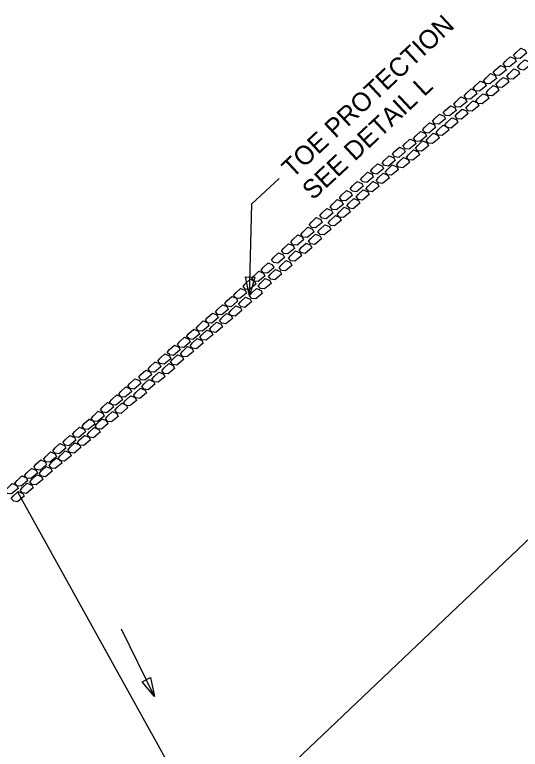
# Model space of a CAD drawing. Extents: x 2384780 to 2405432, y 547869 to 573706.
# Drawn here: x 2398296.7 to 2398431.5, y 559969.6 to 560165.6 of the extents above; entities that cross this region are included whole.
import ezdxf

# ---------------------------------------------------------------- set-up
doc = ezdxf.new("R2010")
doc.units = 0
for name, color, linetype in [('Old_Level_1', 7, 'Continuous'), ('Old_Level_19', 7, 'Continuous'), ('Old_Level_20', 7, 'Continuous'), ('Old_Level_5', 7, 'Continuous')]:
    doc.layers.add(name, color=color, linetype=linetype)

msp = doc.modelspace()

# ---------------------------------------------------------------- linework, layer by layer
at = {"layer": 'Old_Level_1'}
msp.add_line((2398405.81, 559842.88), (2398297.53, 560038.23), dxfattribs=at)
at = {"layer": 'Old_Level_19'}
msp.add_line((2398244.74, 559846.05), (2398525.67, 560113.13), dxfattribs=at)
at = {"layer": 'Old_Level_20'}
for points in [[(2398429.74, 560154.75), (2398430.34, 560155.49), (2398431.61, 560156.68), (2398432.83, 560156.16), (2398433.18, 560155.39), (2398431.43, 560153.93), (2398430.38, 560154.07), (2398429.74, 560154.75)], [(2398426.93, 560152.52), (2398427.53, 560153.26), (2398428.8, 560154.44), (2398430.02, 560153.93), (2398430.37, 560153.16), (2398428.62, 560151.7), (2398427.57, 560151.83), (2398426.93, 560152.52)], [(2398430.79, 560151.68), (2398431.39, 560152.41), (2398432.66, 560153.6), (2398433.88, 560153.08), (2398434.23, 560152.31), (2398432.47, 560150.85), (2398431.43, 560150.99), (2398430.79, 560151.68)], [(2398424.31, 560150.21), (2398424.91, 560150.94), (2398426.19, 560152.13), (2398427.41, 560151.61), (2398427.75, 560150.84), (2398426, 560149.38), (2398424.96, 560149.52), (2398424.31, 560150.21)], [(2398427.9, 560149.25), (2398428.5, 560149.99), (2398429.77, 560151.17), (2398430.99, 560150.66), (2398431.34, 560149.89), (2398429.59, 560148.43), (2398428.54, 560148.56), (2398427.9, 560149.25)], [(2398421.69, 560147.98), (2398422.29, 560148.72), (2398423.56, 560149.91), (2398424.78, 560149.39), (2398425.13, 560148.62), (2398423.37, 560147.16), (2398422.33, 560147.3), (2398421.69, 560147.98)], [(2398418.95, 560146.03), (2398419.55, 560146.77), (2398420.83, 560147.95), (2398422.05, 560147.44), (2398422.39, 560146.67), (2398420.64, 560145.21), (2398419.59, 560145.34), (2398418.95, 560146.03)], [(2398425, 560147.01), (2398425.6, 560147.75), (2398426.87, 560148.93), (2398428.09, 560148.42), (2398428.44, 560147.65), (2398426.68, 560146.19), (2398425.64, 560146.32), (2398425, 560147.01)], [(2398416.51, 560143.91), (2398417.11, 560144.65), (2398418.38, 560145.84), (2398419.6, 560145.32), (2398419.95, 560144.55), (2398418.19, 560143.09), (2398417.15, 560143.23), (2398416.51, 560143.91)], [(2398422.38, 560144.79), (2398422.98, 560145.52), (2398424.25, 560146.71), (2398425.47, 560146.19), (2398425.82, 560145.42), (2398424.06, 560143.96), (2398423.02, 560144.1), (2398422.38, 560144.79)], [(2398413.78, 560141.78), (2398414.38, 560142.51), (2398415.66, 560143.7), (2398416.88, 560143.18), (2398417.22, 560142.41), (2398415.47, 560140.95), (2398414.42, 560141.09), (2398413.78, 560141.78)], [(2398419.65, 560142.65), (2398420.25, 560143.39), (2398421.52, 560144.57), (2398422.74, 560144.06), (2398423.09, 560143.29), (2398421.34, 560141.83), (2398420.29, 560141.96), (2398419.65, 560142.65)], [(2398410.98, 560139.45), (2398411.58, 560140.19), (2398412.85, 560141.37), (2398414.07, 560140.86), (2398414.42, 560140.09), (2398412.66, 560138.63), (2398411.62, 560138.76), (2398410.98, 560139.45)], [(2398417.01, 560140.71), (2398417.61, 560141.44), (2398418.88, 560142.63), (2398420.1, 560142.11), (2398420.45, 560141.34), (2398418.69, 560139.88), (2398417.65, 560140.02), (2398417.01, 560140.71)], [(2398414.1, 560138.56), (2398414.7, 560139.29), (2398415.97, 560140.48), (2398417.19, 560139.96), (2398417.54, 560139.19), (2398415.79, 560137.73), (2398414.74, 560137.87), (2398414.1, 560138.56)], [(2398408.08, 560137.21), (2398408.68, 560137.94), (2398409.95, 560139.13), (2398411.17, 560138.61), (2398411.52, 560137.85), (2398409.76, 560136.39), (2398408.72, 560136.52), (2398408.08, 560137.21)], [(2398411.39, 560136.24), (2398411.99, 560136.97), (2398413.26, 560138.16), (2398414.48, 560137.64), (2398414.83, 560136.87), (2398413.07, 560135.41), (2398412.03, 560135.55), (2398411.39, 560136.24)], [(2398405.46, 560134.89), (2398406.06, 560135.63), (2398407.33, 560136.82), (2398408.55, 560136.3), (2398408.9, 560135.53), (2398407.14, 560134.07), (2398406.1, 560134.21), (2398405.46, 560134.89)], [(2398409.03, 560134.22), (2398409.63, 560134.95), (2398410.9, 560136.14), (2398412.12, 560135.62), (2398412.47, 560134.85), (2398410.71, 560133.39), (2398409.67, 560133.53), (2398409.03, 560134.22)], [(2398403.03, 560132.59), (2398403.63, 560133.33), (2398404.9, 560134.52), (2398406.12, 560134), (2398406.47, 560133.23), (2398404.71, 560131.77), (2398403.67, 560131.9), (2398403.03, 560132.59)], [(2398406.4, 560132.09), (2398407, 560132.82), (2398408.27, 560134.01), (2398409.49, 560133.49), (2398409.84, 560132.72), (2398408.08, 560131.26), (2398407.04, 560131.4), (2398406.4, 560132.09)], [(2398400.21, 560130.54), (2398400.8, 560131.28), (2398402.08, 560132.46), (2398403.3, 560131.95), (2398403.65, 560131.18), (2398401.89, 560129.72), (2398400.85, 560129.85), (2398400.21, 560130.54)], [(2398403.58, 560130.04), (2398404.18, 560130.77), (2398405.45, 560131.96), (2398406.67, 560131.44), (2398407.02, 560130.67), (2398405.26, 560129.21), (2398404.22, 560129.35), (2398403.58, 560130.04)], [(2398397.39, 560128.4), (2398397.99, 560129.13), (2398399.26, 560130.32), (2398400.48, 560129.8), (2398400.83, 560129.04), (2398399.07, 560127.58), (2398398.03, 560127.71), (2398397.39, 560128.4)], [(2398401.15, 560127.64), (2398401.75, 560128.38), (2398403.02, 560129.57), (2398404.24, 560129.05), (2398404.59, 560128.28), (2398402.83, 560126.82), (2398401.79, 560126.95), (2398401.15, 560127.64)], [(2398394.68, 560126.08), (2398395.28, 560126.81), (2398396.55, 560128), (2398397.77, 560127.48), (2398398.12, 560126.71), (2398396.36, 560125.25), (2398395.32, 560125.39), (2398394.68, 560126.08)], [(2398391.59, 560123.92), (2398392.19, 560124.65), (2398393.46, 560125.84), (2398394.68, 560125.32), (2398395.03, 560124.55), (2398393.27, 560123.09), (2398392.23, 560123.23), (2398391.59, 560123.92)], [(2398398.51, 560125.6), (2398399.11, 560126.34), (2398400.38, 560127.53), (2398401.6, 560127.01), (2398401.95, 560126.24), (2398400.2, 560124.78), (2398399.15, 560124.92), (2398398.51, 560125.6)], [(2398395.5, 560123.63), (2398396.1, 560124.37), (2398397.37, 560125.56), (2398398.59, 560125.04), (2398398.94, 560124.27), (2398397.18, 560122.81), (2398396.14, 560122.95), (2398395.5, 560123.63)], [(2398388.87, 560121.69), (2398389.47, 560122.42), (2398390.74, 560123.61), (2398391.96, 560123.09), (2398392.31, 560122.32), (2398390.55, 560120.86), (2398389.51, 560121), (2398388.87, 560121.69)], [(2398393.06, 560121.42), (2398393.66, 560122.16), (2398394.93, 560123.35), (2398396.15, 560122.83), (2398396.5, 560122.06), (2398394.74, 560120.6), (2398393.7, 560120.74), (2398393.06, 560121.42)], [(2398386.13, 560119.22), (2398386.73, 560119.96), (2398388, 560121.14), (2398389.22, 560120.63), (2398389.57, 560119.86), (2398387.81, 560118.4), (2398386.77, 560118.53), (2398386.13, 560119.22)], [(2398390.34, 560119.19), (2398390.94, 560119.93), (2398392.21, 560121.12), (2398393.43, 560120.6), (2398393.78, 560119.83), (2398392.03, 560118.37), (2398390.98, 560118.51), (2398390.34, 560119.19)], [(2398383.25, 560116.78), (2398383.85, 560117.51), (2398385.13, 560118.7), (2398386.35, 560118.18), (2398386.69, 560117.42), (2398384.94, 560115.96), (2398383.89, 560116.09), (2398383.25, 560116.78)], [(2398387.72, 560117), (2398388.32, 560117.74), (2398389.59, 560118.92), (2398390.81, 560118.41), (2398391.16, 560117.64), (2398389.4, 560116.18), (2398388.36, 560116.31), (2398387.72, 560117)], [(2398380.82, 560114.37), (2398381.42, 560115.1), (2398382.69, 560116.29), (2398383.91, 560115.77), (2398384.26, 560115), (2398382.51, 560113.54), (2398381.46, 560113.68), (2398380.82, 560114.37)], [(2398385.28, 560114.68), (2398385.88, 560115.42), (2398387.15, 560116.6), (2398388.37, 560116.09), (2398388.72, 560115.32), (2398386.97, 560113.86), (2398385.92, 560113.99), (2398385.28, 560114.68)], [(2398378.03, 560112.02), (2398378.63, 560112.76), (2398379.9, 560113.94), (2398381.12, 560113.43), (2398381.47, 560112.66), (2398379.71, 560111.2), (2398378.67, 560111.33), (2398378.03, 560112.02)], [(2398382.67, 560112.34), (2398383.27, 560113.08), (2398384.54, 560114.27), (2398385.76, 560113.75), (2398386.11, 560112.98), (2398384.35, 560111.52), (2398383.31, 560111.66), (2398382.67, 560112.34)], [(2398380.31, 560110.12), (2398380.91, 560110.85), (2398382.18, 560112.04), (2398383.4, 560111.52), (2398383.75, 560110.76), (2398382, 560109.3), (2398380.95, 560109.43), (2398380.31, 560110.12)], [(2398375.24, 560109.58), (2398375.84, 560110.32), (2398377.11, 560111.51), (2398378.33, 560110.99), (2398378.68, 560110.22), (2398376.92, 560108.76), (2398375.88, 560108.9), (2398375.24, 560109.58)], [(2398373, 560107.01), (2398373.6, 560107.74), (2398374.87, 560108.93), (2398376.09, 560108.41), (2398376.44, 560107.64), (2398374.68, 560106.18), (2398373.64, 560106.32), (2398373, 560107.01)], [(2398377.52, 560107.68), (2398378.12, 560108.42), (2398379.4, 560109.6), (2398380.62, 560109.09), (2398380.96, 560108.32), (2398379.21, 560106.86), (2398378.17, 560106.99), (2398377.52, 560107.68)], [(2398370.28, 560104.93), (2398370.88, 560105.67), (2398372.15, 560106.86), (2398373.37, 560106.34), (2398373.72, 560105.57), (2398371.96, 560104.11), (2398370.92, 560104.25), (2398370.28, 560104.93)], [(2398375.01, 560105.18), (2398375.61, 560105.91), (2398376.88, 560107.1), (2398378.1, 560106.58), (2398378.45, 560105.81), (2398376.69, 560104.35), (2398375.65, 560104.49), (2398375.01, 560105.18)], [(2398367.84, 560102.61), (2398368.44, 560103.35), (2398369.71, 560104.53), (2398370.93, 560104.02), (2398371.28, 560103.25), (2398369.52, 560101.79), (2398368.48, 560101.92), (2398367.84, 560102.61)], [(2398372.49, 560102.76), (2398373.09, 560103.49), (2398374.36, 560104.68), (2398375.58, 560104.16), (2398375.93, 560103.39), (2398374.17, 560101.94), (2398373.13, 560102.07), (2398372.49, 560102.76)], [(2398365.14, 560100.18), (2398365.74, 560100.92), (2398367.01, 560102.1), (2398368.23, 560101.59), (2398368.58, 560100.82), (2398366.82, 560099.36), (2398365.78, 560099.49), (2398365.14, 560100.18)], [(2398369.68, 560100.68), (2398370.28, 560101.41), (2398371.55, 560102.6), (2398372.77, 560102.08), (2398373.12, 560101.32), (2398371.36, 560099.86), (2398370.32, 560099.99), (2398369.68, 560100.68)], [(2398362.37, 560097.48), (2398362.97, 560098.21), (2398364.24, 560099.4), (2398365.46, 560098.88), (2398365.81, 560098.12), (2398364.05, 560096.66), (2398363.01, 560096.79), (2398362.37, 560097.48)], [(2398367.17, 560098.08), (2398367.77, 560098.82), (2398369.04, 560100.01), (2398370.26, 560099.49), (2398370.61, 560098.72), (2398368.85, 560097.26), (2398367.81, 560097.4), (2398367.17, 560098.08)], [(2398359.93, 560095.25), (2398360.53, 560095.98), (2398361.8, 560097.17), (2398363.02, 560096.65), (2398363.37, 560095.88), (2398361.61, 560094.42), (2398360.57, 560094.56), (2398359.93, 560095.25)], [(2398364.37, 560095.74), (2398364.97, 560096.47), (2398366.25, 560097.66), (2398367.47, 560097.14), (2398367.81, 560096.37), (2398366.06, 560094.91), (2398365.02, 560095.05), (2398364.37, 560095.74)], [(2398357.57, 560093.11), (2398358.17, 560093.84), (2398359.44, 560095.03), (2398360.66, 560094.51), (2398361.01, 560093.75), (2398359.25, 560092.29), (2398358.21, 560092.42), (2398357.57, 560093.11)], [(2398361.59, 560093.3), (2398362.19, 560094.04), (2398363.46, 560095.22), (2398364.68, 560094.71), (2398365.03, 560093.94), (2398363.27, 560092.48), (2398362.23, 560092.61), (2398361.59, 560093.3)], [(2398355.05, 560090.69), (2398355.64, 560091.43), (2398356.92, 560092.61), (2398358.14, 560092.1), (2398358.49, 560091.33), (2398356.73, 560089.87), (2398355.69, 560090), (2398355.05, 560090.69)], [(2398359.26, 560090.63), (2398359.86, 560091.36), (2398361.14, 560092.55), (2398362.36, 560092.03), (2398362.7, 560091.26), (2398360.95, 560089.8), (2398359.9, 560089.94), (2398359.26, 560090.63)], [(2398352.69, 560088.55), (2398353.28, 560089.29), (2398354.56, 560090.48), (2398355.78, 560089.96), (2398356.12, 560089.19), (2398354.37, 560087.73), (2398353.33, 560087.87), (2398352.69, 560088.55)], [(2398356.37, 560088.36), (2398356.97, 560089.1), (2398358.25, 560090.29), (2398359.47, 560089.77), (2398359.81, 560089), (2398358.06, 560087.54), (2398357.02, 560087.68), (2398356.37, 560088.36)], [(2398350.2, 560086.34), (2398350.8, 560087.07), (2398352.08, 560088.26), (2398353.3, 560087.74), (2398353.64, 560086.97), (2398351.89, 560085.51), (2398350.85, 560085.65), (2398350.2, 560086.34)], [(2398353.76, 560086.03), (2398354.36, 560086.76), (2398355.63, 560087.95), (2398356.85, 560087.43), (2398357.2, 560086.67), (2398355.44, 560085.21), (2398354.4, 560085.34), (2398353.76, 560086.03)], [(2398347.52, 560084.12), (2398348.12, 560084.85), (2398349.39, 560086.04), (2398350.61, 560085.52), (2398350.96, 560084.75), (2398349.21, 560083.29), (2398348.16, 560083.43), (2398347.52, 560084.12)], [(2398351.3, 560083.97), (2398351.9, 560084.71), (2398353.17, 560085.9), (2398354.39, 560085.38), (2398354.74, 560084.61), (2398352.99, 560083.15), (2398351.94, 560083.29), (2398351.3, 560083.97)], [(2398345.04, 560082), (2398345.64, 560082.74), (2398346.91, 560083.92), (2398348.13, 560083.41), (2398348.48, 560082.64), (2398346.73, 560081.18), (2398345.68, 560081.31), (2398345.04, 560082)], [(2398348.63, 560081.7), (2398349.23, 560082.43), (2398350.5, 560083.62), (2398351.72, 560083.1), (2398352.07, 560082.34), (2398350.32, 560080.88), (2398349.27, 560081.01), (2398348.63, 560081.7)], [(2398342.52, 560079.79), (2398343.12, 560080.53), (2398344.4, 560081.72), (2398345.62, 560081.2), (2398345.96, 560080.43), (2398344.21, 560078.97), (2398343.17, 560079.11), (2398342.52, 560079.79)], [(2398346.04, 560079.57), (2398346.64, 560080.31), (2398347.91, 560081.5), (2398349.13, 560080.98), (2398349.48, 560080.21), (2398347.73, 560078.75), (2398346.68, 560078.89), (2398346.04, 560079.57)], [(2398340.06, 560077.64), (2398340.66, 560078.38), (2398341.93, 560079.57), (2398343.15, 560079.05), (2398343.5, 560078.28), (2398341.74, 560076.82), (2398340.7, 560076.96), (2398340.06, 560077.64)], [(2398343.47, 560077.31), (2398344.07, 560078.05), (2398345.35, 560079.23), (2398346.57, 560078.72), (2398346.91, 560077.95), (2398345.16, 560076.49), (2398344.12, 560076.62), (2398343.47, 560077.31)], [(2398337.37, 560075.53), (2398337.97, 560076.27), (2398339.24, 560077.46), (2398340.46, 560076.94), (2398340.81, 560076.17), (2398339.05, 560074.71), (2398338.01, 560074.85), (2398337.37, 560075.53)], [(2398340.9, 560075.15), (2398341.5, 560075.89), (2398342.77, 560077.07), (2398343.99, 560076.56), (2398344.34, 560075.79), (2398342.58, 560074.33), (2398341.54, 560074.46), (2398340.9, 560075.15)], [(2398334.86, 560073.22), (2398335.46, 560073.95), (2398336.73, 560075.14), (2398337.95, 560074.62), (2398338.3, 560073.85), (2398336.54, 560072.39), (2398335.5, 560072.53), (2398334.86, 560073.22)], [(2398338.21, 560072.99), (2398338.81, 560073.72), (2398340.08, 560074.91), (2398341.3, 560074.39), (2398341.65, 560073.62), (2398339.9, 560072.16), (2398338.85, 560072.3), (2398338.21, 560072.99)], [(2398332.23, 560071.06), (2398332.83, 560071.79), (2398334.1, 560072.98), (2398335.32, 560072.46), (2398335.67, 560071.69), (2398333.91, 560070.23), (2398332.87, 560070.37), (2398332.23, 560071.06)], [(2398329.73, 560068.91), (2398330.33, 560069.64), (2398331.6, 560070.83), (2398332.82, 560070.31), (2398333.17, 560069.54), (2398331.41, 560068.08), (2398330.37, 560068.22), (2398329.73, 560068.91)], [(2398335.87, 560070.63), (2398336.47, 560071.36), (2398337.74, 560072.55), (2398338.96, 560072.03), (2398339.31, 560071.27), (2398337.55, 560069.81), (2398336.51, 560069.94), (2398335.87, 560070.63)], [(2398333.25, 560068.36), (2398333.84, 560069.1), (2398335.12, 560070.28), (2398336.34, 560069.77), (2398336.69, 560069), (2398334.93, 560067.54), (2398333.89, 560067.67), (2398333.25, 560068.36)], [(2398326.86, 560066.59), (2398327.46, 560067.32), (2398328.73, 560068.51), (2398329.95, 560067.99), (2398330.3, 560067.22), (2398328.54, 560065.76), (2398327.5, 560065.9), (2398326.86, 560066.59)], [(2398330.58, 560066.39), (2398331.18, 560067.12), (2398332.46, 560068.31), (2398333.68, 560067.79), (2398334.02, 560067.02), (2398332.27, 560065.56), (2398331.23, 560065.7), (2398330.58, 560066.39)], [(2398324.4, 560064.38), (2398325, 560065.12), (2398326.27, 560066.31), (2398327.49, 560065.79), (2398327.84, 560065.02), (2398326.08, 560063.56), (2398325.04, 560063.7), (2398324.4, 560064.38)], [(2398328.36, 560064.06), (2398328.96, 560064.8), (2398330.23, 560065.98), (2398331.45, 560065.47), (2398331.8, 560064.7), (2398330.04, 560063.24), (2398329, 560063.37), (2398328.36, 560064.06)], [(2398321.99, 560062.24), (2398322.58, 560062.97), (2398323.86, 560064.16), (2398325.08, 560063.64), (2398325.43, 560062.87), (2398323.67, 560061.41), (2398322.63, 560061.55), (2398321.99, 560062.24)], [(2398325.72, 560062.06), (2398326.32, 560062.79), (2398327.59, 560063.98), (2398328.81, 560063.46), (2398329.16, 560062.69), (2398327.4, 560061.23), (2398326.36, 560061.37), (2398325.72, 560062.06)], [(2398319.56, 560060.25), (2398320.16, 560060.99), (2398321.43, 560062.17), (2398322.65, 560061.66), (2398323, 560060.89), (2398321.25, 560059.43), (2398320.2, 560059.56), (2398319.56, 560060.25)], [(2398323.35, 560060.07), (2398323.95, 560060.81), (2398325.22, 560062), (2398326.44, 560061.48), (2398326.79, 560060.71), (2398325.04, 560059.25), (2398323.99, 560059.39), (2398323.35, 560060.07)], [(2398317.06, 560057.88), (2398317.66, 560058.62), (2398318.93, 560059.81), (2398320.15, 560059.29), (2398320.5, 560058.52), (2398318.74, 560057.06), (2398317.7, 560057.2), (2398317.06, 560057.88)], [(2398320.84, 560057.81), (2398321.44, 560058.55), (2398322.71, 560059.74), (2398323.93, 560059.22), (2398324.28, 560058.45), (2398322.52, 560056.99), (2398321.48, 560057.13), (2398320.84, 560057.81)], [(2398314.62, 560055.77), (2398315.21, 560056.51), (2398316.49, 560057.69), (2398317.71, 560057.18), (2398318.06, 560056.41), (2398316.3, 560054.95), (2398315.26, 560055.08), (2398314.62, 560055.77)], [(2398318.1, 560055.86), (2398318.7, 560056.59), (2398319.97, 560057.78), (2398321.19, 560057.26), (2398321.54, 560056.49), (2398319.78, 560055.03), (2398318.74, 560055.17), (2398318.1, 560055.86)], [(2398312.08, 560053.68), (2398312.68, 560054.41), (2398313.96, 560055.6), (2398315.18, 560055.08), (2398315.52, 560054.31), (2398313.77, 560052.85), (2398312.73, 560052.99), (2398312.08, 560053.68)], [(2398315.98, 560053.57), (2398316.58, 560054.31), (2398317.85, 560055.49), (2398319.07, 560054.98), (2398319.42, 560054.21), (2398317.66, 560052.75), (2398316.62, 560052.88), (2398315.98, 560053.57)], [(2398309.53, 560051.46), (2398310.13, 560052.19), (2398311.4, 560053.38), (2398312.63, 560052.86), (2398312.97, 560052.09), (2398311.22, 560050.63), (2398310.17, 560050.77), (2398309.53, 560051.46)], [(2398313.39, 560051.47), (2398313.99, 560052.21), (2398315.27, 560053.39), (2398316.49, 560052.88), (2398316.83, 560052.11), (2398315.08, 560050.65), (2398314.04, 560050.78), (2398313.39, 560051.47)], [(2398306.84, 560049.29), (2398307.44, 560050.03), (2398308.71, 560051.22), (2398309.93, 560050.7), (2398310.28, 560049.93), (2398308.52, 560048.47), (2398307.48, 560048.6), (2398306.84, 560049.29)], [(2398310.83, 560049.47), (2398311.43, 560050.21), (2398312.7, 560051.4), (2398313.92, 560050.88), (2398314.27, 560050.11), (2398312.51, 560048.65), (2398311.47, 560048.79), (2398310.83, 560049.47)], [(2398308.24, 560047.32), (2398308.84, 560048.05), (2398310.12, 560049.24), (2398311.34, 560048.72), (2398311.68, 560047.95), (2398309.93, 560046.49), (2398308.89, 560046.63), (2398308.24, 560047.32)], [(2398304.38, 560047.03), (2398304.97, 560047.77), (2398306.25, 560048.95), (2398307.47, 560048.44), (2398307.81, 560047.67), (2398306.06, 560046.21), (2398305.02, 560046.34), (2398304.38, 560047.03)], [(2398305.82, 560045.34), (2398306.42, 560046.08), (2398307.69, 560047.26), (2398308.91, 560046.75), (2398309.26, 560045.98), (2398307.5, 560044.52), (2398306.46, 560044.65), (2398305.82, 560045.34)], [(2398301.73, 560044.93), (2398302.33, 560045.66), (2398303.6, 560046.85), (2398304.82, 560046.33), (2398305.17, 560045.57), (2398303.42, 560044.11), (2398302.37, 560044.24), (2398301.73, 560044.93)], [(2398299.27, 560042.67), (2398299.87, 560043.4), (2398301.14, 560044.59), (2398302.36, 560044.07), (2398302.71, 560043.31), (2398300.95, 560041.85), (2398299.91, 560041.98), (2398299.27, 560042.67)], [(2398303.18, 560043.18), (2398303.78, 560043.92), (2398305.05, 560045.11), (2398306.27, 560044.59), (2398306.62, 560043.82), (2398304.86, 560042.36), (2398303.82, 560042.49), (2398303.18, 560043.18)], [(2398296.68, 560040.63), (2398297.28, 560041.36), (2398298.55, 560042.55), (2398299.77, 560042.03), (2398300.12, 560041.26), (2398298.36, 560039.8), (2398297.32, 560039.94), (2398296.68, 560040.63)], [(2398300.71, 560040.98), (2398301.31, 560041.71), (2398302.58, 560042.9), (2398303.8, 560042.38), (2398304.15, 560041.62), (2398302.4, 560040.16), (2398301.35, 560040.29), (2398300.71, 560040.98)], [(2398294.12, 560038.57), (2398294.71, 560039.31), (2398295.99, 560040.5), (2398297.21, 560039.98), (2398297.55, 560039.21), (2398295.8, 560037.75), (2398294.76, 560037.89), (2398294.12, 560038.57)], [(2398298.14, 560038.71), (2398298.74, 560039.45), (2398300.01, 560040.63), (2398301.23, 560040.12), (2398301.58, 560039.35), (2398299.82, 560037.89), (2398298.78, 560038.02), (2398298.14, 560038.71)], [(2398295.75, 560036.5), (2398296.35, 560037.24), (2398297.62, 560038.42), (2398298.84, 560037.91), (2398299.19, 560037.14), (2398297.44, 560035.68), (2398296.39, 560035.81), (2398295.75, 560036.5)]]:
    msp.add_lwpolyline(points, dxfattribs=at)
at = {"layer": 'Old_Level_5'}
for p, q in [((2398367.23, 560121.95), (2398359.92, 560115.13)), ((2398359.32, 560090.62), (2398359.92, 560115.13)), ((2398333.97, 559983.71), (2398325.11, 560001.63))]:
    msp.add_line(p, q, dxfattribs=at)
for points in [[(2398360.69, 560095.59), (2398359.32, 560090.62), (2398358.19, 560095.65)], [(2398332.87, 559988.75), (2398333.97, 559983.71), (2398330.63, 559987.64)]]:
    msp.add_lwpolyline(points, close=True, dxfattribs=at)

# ---------------------------------------------------------------- texts
for s, p in [('TOE PROTECTION', (2398370.77, 560121.83)), ('SEE DETAIL L', (2398376.22, 560115.98))]:
    msp.add_text(s, height=5, rotation=43, dxfattribs=at).set_placement(p)

doc.saveas('drawing.dxf')
